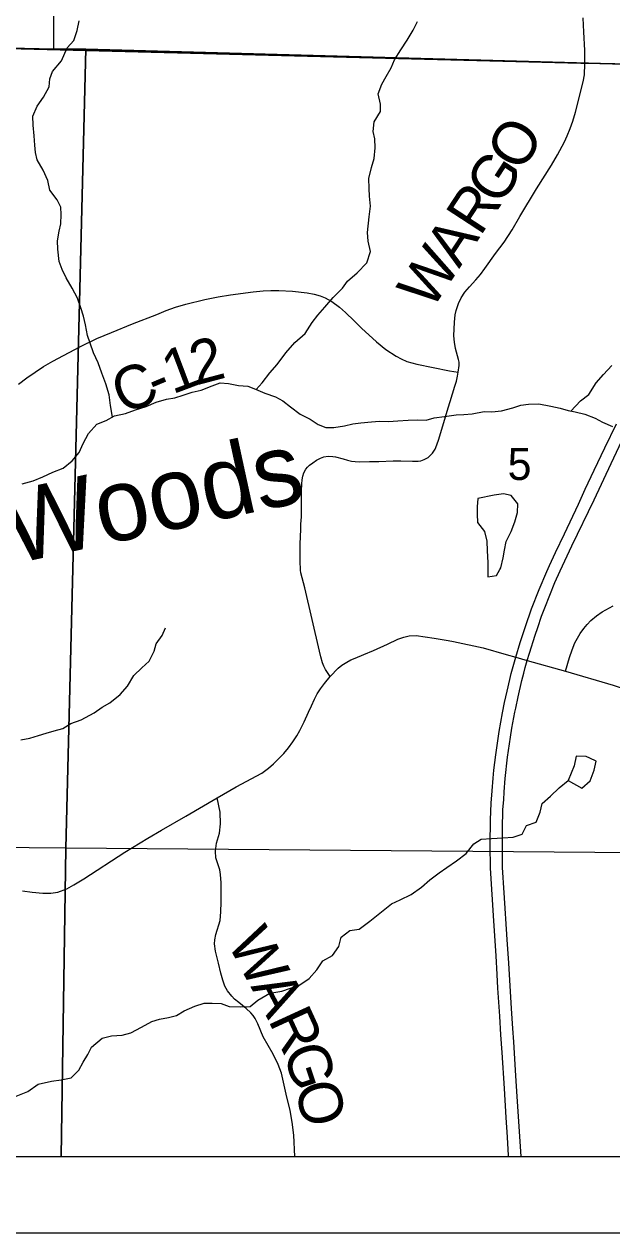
# Model space of a CAD drawing. Extents: x 0 to 34, y 0 to 22.
# Drawn here: x 6.329 to 7.097, y 14 to 15.58 of the extents above; entities that cross this region are included whole.
import ezdxf

# ---------------------------------------------------------------- set-up
doc = ezdxf.new("R2010")
doc.units = 0
for name, color, linetype in [('GM_X_Corporation', 7, 'Continuous'), ('GM_X_County_Road', 7, 'Continuous'), ('GM_X_County_Road_Text', 7, 'Continuous'), ('GM_X_Interstate_Route', 7, 'Continuous'), ('GM_X_Minor_Lake', 7, 'Continuous'), ('GM_X_Minor_River', 7, 'Continuous'), ('GM_X_Minor_River_Text', 7, 'Continuous'), ('GM_X_Section_Text', 7, 'Continuous'), ('SH_Data', 7, 'Continuous')]:
    doc.layers.add(name, color=color, linetype=linetype)

msp = doc.modelspace()

# ---------------------------------------------------------------- linework, layer by layer
at = {"layer": 'GM_X_Corporation'}
for points in [[(5.3699, 17.5116), (5.3543, 16.3597), (5.3453, 15.7118), (5.3483, 15.5723), (5.5099, 15.5686), (5.5173, 15.5684), (5.5624, 15.5674), (5.5643, 15.5673), (5.624, 15.566), (5.6266, 15.5659), (7.0561, 15.5293), (7.0614, 15.5292), (7.2766, 15.5247), (7.2802, 15.5246), (7.2927, 15.5244), (7.5593, 15.5188), (7.5629, 15.5187), (8.3936, 15.4979)], [(8.3936, 15.4979), (7.5629, 15.5187), (7.5593, 15.5188), (7.2927, 15.5244), (7.2802, 15.5246), (7.2766, 15.5247), (7.0614, 15.5292), (7.0561, 15.5293), (5.6266, 15.5659)], [(2.1, 14.1), (8.9, 14.1)], [(4.3124, 14.1), (8.9, 14.1)]]:
    msp.add_lwpolyline(points, dxfattribs=at)
for points in [[(7.3577, 16.5425), (7.3478, 15.5216), (6.4093, 15.5478), (6.3676, 15.5481), (6.3626, 16.5761)], [(5.3476, 15.5712), (6.3676, 15.5481), (6.4093, 15.5478), (6.383, 14.5028), (5.3249, 14.5126), (5.3254, 14.5744)], [(6.4093, 15.5478), (7.3478, 15.5216), (7.4137, 15.5211), (7.3933, 14.4947), (6.383, 14.5028)], [(5.3175, 14.1), (6.3769, 14.1), (6.383, 14.5028), (5.3249, 14.5126)], [(6.3769, 14.1), (7.3859, 14.1), (7.3933, 14.4947), (6.383, 14.5028)]]:
    msp.add_lwpolyline(points, close=True, dxfattribs=at)
at = {"layer": 'GM_X_County_Road'}
for points in [[(7.0616, 15.5316), (7.0616, 15.5461), (7.0601, 15.5705), (7.0597, 15.5792), (7.0593, 15.5885)], [(6.8853, 15.0872), (6.8915, 15.107), (6.8935, 15.1138), (6.895, 15.12), (6.8957, 15.1254), (6.8972, 15.1339), (6.897, 15.1386), (6.8964, 15.1421), (6.8925, 15.1562), (6.8912, 15.1645), (6.89, 15.1727), (6.8909, 15.1908), (6.8919, 15.2002), (6.8933, 15.2061), (6.8963, 15.2151), (6.8996, 15.2227), (6.9047, 15.2298), (6.9107, 15.2369), (6.9191, 15.2459), (6.9251, 15.2531), (6.9306, 15.2611), (6.9448, 15.2807), (6.9561, 15.2952), (6.9663, 15.3116), (6.9765, 15.3287), (6.9984, 15.365), (7.0177, 15.3961), (7.0258, 15.4096), (7.035, 15.4267), (7.0384, 15.4344), (7.0423, 15.4438), (7.0458, 15.4536), (7.0492, 15.4654), (7.0593, 15.505), (7.0608, 15.5142), (7.0616, 15.5287), (7.0616, 15.5316)], [(6.3211, 15.1096), (6.3322, 15.1181), (6.3429, 15.1255), (6.354, 15.1326), (6.3661, 15.1399), (6.4014, 15.1587), (6.4236, 15.1694), (6.4426, 15.1773), (6.4704, 15.1885), (6.502, 15.2006), (6.5142, 15.2061), (6.5262, 15.2105), (6.5401, 15.2141), (6.5649, 15.2205), (6.5822, 15.2238), (6.5985, 15.2266), (6.6281, 15.2306), (6.6408, 15.2316), (6.6509, 15.2321), (6.6616, 15.2321), (6.6793, 15.2315), (6.6983, 15.2291), (6.7076, 15.2272), (6.7154, 15.2251), (6.7222, 15.2224), (6.7306, 15.2179), (6.7408, 15.2102), (6.7488, 15.2034), (6.7598, 15.1924), (6.7696, 15.1831), (6.7891, 15.1649), (6.8013, 15.1549), (6.8149, 15.1461), (6.8214, 15.1426), (6.8288, 15.1394), (6.842, 15.136), (6.8844, 15.1271), (6.8957, 15.1254)], [(6.7286, 14.7275), (6.7223, 14.7366), (6.7202, 14.7408), (6.7186, 14.7452), (6.7162, 14.753), (6.7145, 14.7604), (6.6956, 14.8434), (6.6904, 14.8628), (6.6899, 14.8664), (6.6896, 14.8707), (6.6894, 14.8742), (6.6892, 14.8794), (6.6895, 14.9003), (6.6901, 14.9203), (6.6904, 14.9267), (6.6909, 14.9363), (6.6911, 14.9427), (6.6913, 14.9569), (6.6913, 14.9697), (6.6915, 14.9794), (6.6919, 14.9844), (6.6928, 14.9892), (6.6943, 14.9936), (6.6968, 14.9984), (6.6989, 15.001), (6.7017, 15.0036), (6.7059, 15.007), (6.7108, 15.0103), (6.716, 15.0131), (6.7202, 15.0146), (6.7261, 15.0155), (6.7319, 15.0151), (6.7356, 15.0145), (6.7455, 15.0122), (6.751, 15.0105), (6.7566, 15.0089), (6.7614, 15.0085), (6.7666, 15.0083), (6.7798, 15.0084), (6.792, 15.0085), (6.811, 15.0096), (6.821, 15.0096), (6.8362, 15.0089), (6.8436, 15.009), (6.847, 15.0095), (6.8514, 15.011), (6.8566, 15.014), (6.8594, 15.0163), (6.8625, 15.0196), (6.8656, 15.0248), (6.868, 15.0303), (6.8707, 15.0376), (6.8791, 15.0668), (6.8826, 15.0787), (6.8853, 15.0872)], [(7.0363, 14.7345), (7.0413, 14.7524), (7.0447, 14.7622), (7.0484, 14.7716), (7.0517, 14.7777), (7.0551, 14.7835), (7.0599, 14.79), (7.0645, 14.7955), (7.0694, 14.8005), (7.0767, 14.8068), (7.084, 14.8119), (7.0982, 14.8198)], [(6.7286, 14.7275), (6.739, 14.7382), (6.7438, 14.7421), (6.7502, 14.746), (6.7557, 14.7491), (6.7612, 14.7515), (6.7727, 14.7562), (6.7854, 14.7615), (6.8036, 14.7699), (6.8171, 14.7761), (6.8247, 14.779), (6.8316, 14.7806), (6.841, 14.7809), (6.8644, 14.7777), (6.8828, 14.7743)], [(6.8828, 14.7743), (6.8896, 14.7731), (6.9286, 14.7649), (6.9585, 14.7561), (6.9711, 14.7526), (6.986, 14.7484), (7.0363, 14.7345), (7.0982, 14.716), (7.1152, 14.7105), (7.1287, 14.7049), (7.1395, 14.6983), (7.1586, 14.6855), (7.1616, 14.6831)], [(6.581, 14.5686), (6.6059, 14.583), (6.6394, 14.6012), (6.6481, 14.6075), (6.6546, 14.6132), (6.6679, 14.6268), (6.6742, 14.6342), (6.6796, 14.6418), (6.6849, 14.6499), (6.689, 14.657), (6.6947, 14.6681), (6.7004, 14.6806), (6.7042, 14.689), (6.708, 14.6979), (6.7115, 14.7047), (6.7158, 14.7111), (6.7212, 14.7184), (6.7286, 14.7275)], [(6.3263, 14.4472), (6.3393, 14.4454), (6.353, 14.4441), (6.3636, 14.4443), (6.3728, 14.4455), (6.3842, 14.4498), (6.3937, 14.455), (6.4064, 14.4628), (6.4604, 14.4977), (6.4902, 14.5161), (6.5083, 14.5267), (6.5398, 14.5449), (6.581, 14.5686)], [(6.6825, 14.1), (6.6812, 14.1278), (6.6789, 14.1446), (6.6762, 14.1599), (6.6712, 14.1813), (6.665, 14.2086), (6.6605, 14.2203), (6.6541, 14.2338), (6.641, 14.2563), (6.6342, 14.2731), (6.6306, 14.2804), (6.6279, 14.284), (6.625, 14.2877), (6.6188, 14.2932), (6.6092, 14.3011), (6.6037, 14.3056), (6.5999, 14.3095), (6.5945, 14.3165), (6.5911, 14.3225), (6.5882, 14.3303), (6.5855, 14.3395), (6.5826, 14.3527), (6.5787, 14.3681), (6.5775, 14.378), (6.5777, 14.383), (6.5791, 14.39), (6.5846, 14.4083), (6.5858, 14.4199), (6.5859, 14.4324), (6.5859, 14.4577), (6.5853, 14.4685), (6.5843, 14.4745), (6.5828, 14.4799), (6.5793, 14.4903), (6.5785, 14.4991), (6.5799, 14.5095), (6.584, 14.5227), (6.5851, 14.535), (6.5848, 14.5502), (6.581, 14.5686)]]:
    msp.add_lwpolyline(points, dxfattribs=at)
at = {"layer": 'GM_X_Interstate_Route'}
for points in [[(6.978, 14.1), (6.9728, 14.1782), (6.971, 14.2053), (6.9684, 14.2497), (6.9673, 14.2673), (6.9657, 14.2932), (6.9644, 14.3155), (6.9621, 14.3527), (6.9599, 14.3836), (6.9561, 14.4445), (6.9539, 14.4779), (6.9536, 14.5065), (6.9536, 14.5129), (6.9537, 14.5277), (6.9543, 14.5534), (6.9554, 14.5661), (6.956, 14.5768), (6.9574, 14.5941), (6.9603, 14.622), (6.9641, 14.6481), (6.9661, 14.6597), (6.9699, 14.6806), (6.971, 14.6861), (6.9742, 14.7009), (6.9792, 14.7221), (6.9818, 14.7319), (6.9836, 14.7393), (6.986, 14.7484), (6.9892, 14.758), (6.9966, 14.7815), (6.9998, 14.7915), (7.0049, 14.8062), (7.0091, 14.8173), (7.0222, 14.8502), (7.0292, 14.8655), (7.0446, 14.8984), (7.0734, 14.9583), (7.096, 15.0059), (7.1278, 15.0734)], [(6.9618, 14.1), (6.9617, 14.1009), (6.9605, 14.1251), (6.9586, 14.1507), (6.9562, 14.1887), (6.9532, 14.2357), (6.9518, 14.259), (6.9504, 14.2834), (6.9479, 14.3197), (6.947, 14.3379), (6.9454, 14.3621), (6.9441, 14.3816), (6.9426, 14.4079), (6.9402, 14.4423), (6.9383, 14.477), (6.9377, 14.5074), (6.938, 14.5398), (6.9391, 14.5617), (6.9402, 14.5778), (6.9417, 14.5947), (6.9426, 14.6051), (6.9449, 14.625), (6.9494, 14.6554), (6.9538, 14.6799), (6.9565, 14.6935), (6.9599, 14.7083), (6.9634, 14.7237), (6.9653, 14.7313), (6.9711, 14.7526), (6.977, 14.7717), (6.9838, 14.7927), (6.9918, 14.8161), (7.0017, 14.8413), (7.0117, 14.8649), (7.0153, 14.8724), (7.0229, 14.8897), (7.0346, 14.9141), (7.053, 14.9528), (7.0619, 14.9722), (7.0738, 14.9971), (7.0874, 15.0263), (7.1026, 15.0579)]]:
    msp.add_lwpolyline(points, dxfattribs=at)
at = {"layer": 'GM_X_Minor_Lake'}
for points in [[(6.9216, 14.96), (6.9205, 14.9493), (6.9206, 14.9399), (6.9213, 14.9289), (6.9301, 14.9171), (6.9332, 14.9046), (6.9339, 14.8918), (6.9344, 14.8766), (6.9344, 14.8576), (6.9458, 14.8596), (6.9505, 14.8674)], [(6.9505, 14.8674), (6.9518, 14.8694), (6.9548, 14.8827), (6.9563, 14.8926), (6.9585, 14.904), (6.9653, 14.9169), (6.9698, 14.9298), (6.9736, 14.9419), (6.9739, 14.9533), (6.9652, 14.9639), (6.9549, 14.9661), (6.9428, 14.9646), (6.9216, 14.96)], [(7.0678, 14.6207), (7.0631, 14.623), (7.0502, 14.6233), (7.0473, 14.6108), (7.0397, 14.5914)], [(7.0397, 14.5914), (7.0576, 14.5813), (7.0685, 14.5908), (7.0738, 14.6048), (7.0764, 14.6166), (7.0678, 14.6207)]]:
    msp.add_lwpolyline(points, dxfattribs=at)
at = {"layer": 'GM_X_Minor_River'}
for points in [[(6.4439, 15.0666), (6.4415, 15.0819), (6.4396, 15.0959), (6.4354, 15.1099), (6.4301, 15.1239), (6.4255, 15.1375), (6.4194, 15.1508), (6.4148, 15.1633), (6.4114, 15.1735), (6.4087, 15.1872), (6.406, 15.1985), (6.4029, 15.2095), (6.3983, 15.222), (6.3915, 15.2352), (6.3835, 15.2489), (6.3782, 15.2595), (6.3743, 15.2701), (6.3728, 15.286), (6.3724, 15.297), (6.3742, 15.3099), (6.3765, 15.3194), (6.3772, 15.3315), (6.3764, 15.341), (6.3718, 15.3508), (6.3623, 15.3633), (6.3596, 15.3762), (6.3535, 15.3894), (6.3455, 15.403), (6.3436, 15.4125), (6.3425, 15.422), (6.3417, 15.4345), (6.3405, 15.4485), (6.3401, 15.4599), (6.3457, 15.4732), (6.354, 15.485), (6.3612, 15.4983), (6.3623, 15.5089), (6.3656, 15.5184), (6.3773, 15.5324), (6.3849, 15.5495), (6.3935, 15.559), (6.3977, 15.5723), (6.4007, 15.5848)], [(6.6317, 15.1027), (6.6395, 15.1114), (6.6497, 15.1243), (6.6591, 15.1353), (6.6704, 15.1505), (6.6825, 15.1642), (6.6961, 15.176), (6.7051, 15.1901), (6.7123, 15.2), (6.7217, 15.2103), (6.7323, 15.2228), (6.7447, 15.235), (6.7511, 15.2445), (6.764, 15.2551), (6.7764, 15.2685), (6.7813, 15.2833), (6.7783, 15.2965), (6.7775, 15.3079), (6.7797, 15.3284), (6.7811, 15.3424), (6.78, 15.3553), (6.7796, 15.3655), (6.7791, 15.3788), (6.7825, 15.3928), (6.7859, 15.4046), (6.7873, 15.4186), (6.7869, 15.4304), (6.7846, 15.4399), (6.7861, 15.4528), (6.7944, 15.4664), (6.7944, 15.4759), (6.7913, 15.4895), (6.7962, 15.5021), (6.8018, 15.5119), (6.8082, 15.5233), (6.8128, 15.5336), (6.821, 15.5469), (6.8293, 15.5594), (6.8372, 15.5727), (6.8425, 15.5837)], [(7.0431, 15.0745), (7.0557, 15.0878), (7.0666, 15.0962), (7.0764, 15.1114), (7.0858, 15.1224), (7.0968, 15.1342)], [(6.326, 14.9795), (6.3404, 14.9833), (6.3532, 14.9883), (6.3661, 14.9944), (6.3797, 14.9998), (6.3914, 15.0093), (6.4005, 15.0203), (6.4057, 15.0321), (6.4129, 15.045), (6.4238, 15.0572), (6.4359, 15.0621), (6.4469, 15.0682), (6.4609, 15.0713), (6.4741, 15.0763), (6.4881, 15.0805), (6.501, 15.0862), (6.5146, 15.0901), (6.5256, 15.092), (6.5365, 15.0955), (6.5483, 15.0993), (6.56, 15.102), (6.5744, 15.1074), (6.5849, 15.1116), (6.5956, 15.1105), (6.6088, 15.1079), (6.6209, 15.1071), (6.6308, 15.103), (6.6433, 15.0981), (6.6569, 15.0932), (6.6668, 15.088), (6.6767, 15.08), (6.6892, 15.0706), (6.7025, 15.0638), (6.7127, 15.057), (6.7229, 15.0529), (6.7335, 15.0529), (6.7472, 15.0553), (6.7581, 15.0576), (6.7687, 15.0591), (6.7824, 15.0603), (6.793, 15.0611)], [(6.793, 15.0611), (6.8047, 15.0608), (6.8168, 15.0616), (6.8304, 15.0628), (6.8422, 15.0632), (6.8539, 15.0625), (6.8645, 15.0655), (6.8778, 15.0675), (6.8933, 15.0694), (6.9031, 15.0699), (6.9141, 15.0707), (6.93, 15.0741), (6.9398, 15.0734), (6.9523, 15.0746), (6.9671, 15.0788), (6.9777, 15.0823), (6.9879, 15.0834), (7.0011, 15.0839), (7.0171, 15.0809), (7.0292, 15.0783), (7.0394, 15.0753), (7.0489, 15.0734), (7.0614, 15.0704), (7.0747, 15.0652), (7.0845, 15.0599), (7.0974, 15.0542)], [(6.3244, 14.6446), (6.3361, 14.6466), (6.3474, 14.6504), (6.3573, 14.6535), (6.3679, 14.6562), (6.3792, 14.6596), (6.3898, 14.6661), (6.403, 14.6707), (6.42, 14.6799), (6.4306, 14.6875), (6.4408, 14.6928), (6.454, 14.7039), (6.4635, 14.7149), (6.4718, 14.7286), (6.4823, 14.7389), (6.4921, 14.7476), (6.4985, 14.7605), (6.5012, 14.77), (6.5091, 14.781), (6.5132, 14.7909)], [(6.5863, 14.2997), (6.5965, 14.296), (6.6109, 14.2953), (6.6238, 14.2961), (6.634, 14.3041), (6.6498, 14.3132), (6.6654, 14.3159), (6.6767, 14.3198), (6.6877, 14.3236), (6.7009, 14.3324), (6.7111, 14.3441), (6.719, 14.3555), (6.7315, 14.3628), (6.7398, 14.3742), (6.7431, 14.3864), (6.7541, 14.3951), (6.7666, 14.3971), (6.7802, 14.4073), (6.7957, 14.4199), (6.8089, 14.4302), (6.8199, 14.4352), (6.8346, 14.4424), (6.8478, 14.452), (6.8588, 14.4615), (6.8709, 14.4706), (6.8811, 14.4779), (6.8935, 14.4866), (6.9064, 14.4961), (6.9162, 14.5087), (6.926, 14.5148), (6.9393, 14.5156), (6.9544, 14.5164), (6.9676, 14.5172), (6.9794, 14.5214), (6.985, 14.5325), (6.9979, 14.537), (7.0028, 14.55), (7.0058, 14.5613), (7.0163, 14.5709), (7.0277, 14.5819), (7.0397, 14.5914)], [(6.3137, 14.177), (6.3333, 14.1847), (6.3469, 14.1946), (6.3643, 14.1981), (6.3772, 14.2), (6.3901, 14.2027), (6.3999, 14.2126), (6.4059, 14.2232), (6.4119, 14.2331), (6.4168, 14.2426), (6.4304, 14.2544), (6.4429, 14.2575), (6.4565, 14.2583), (6.4679, 14.2614), (6.4819, 14.269), (6.4955, 14.2763), (6.5057, 14.2793), (6.5174, 14.2816), (6.5276, 14.284), (6.5378, 14.2901), (6.5515, 14.2962), (6.5639, 14.3004), (6.5742, 14.3004), (6.5863, 14.2997)]]:
    msp.add_lwpolyline(points, dxfattribs=at)
at = {"layer": 'SH_Data'}
for p, q in [((2.1, 14.1), (8.9, 14.1)), ((2, 14), (9, 14))]:
    msp.add_line(p, q, dxfattribs=at)

# ---------------------------------------------------------------- texts
at = {"layer": 'GM_X_County_Road_Text'}
for s, rotation, p in [('O', 59.3741, (6.9789, 15.3853)), ('G', 56.9469, (6.9502, 15.3411)), ('R', 56.8652, (6.9247, 15.302)), ('A', 56.7204, (6.8971, 15.26)), ('W', 56.5977, (6.8608, 15.205)), ('1', 20.662, (6.5223, 15.0961)), ('2', 14.8516, (6.5536, 15.108)), ('C', 23.1053, (6.4584, 15.069)), ('-', 22.764, (6.5012, 15.0873)), ('W', 298.0264, (6.5931, 14.3801)), ('A', 297.9011, (6.6241, 14.3221)), ('R', 294.6762, (6.6471, 14.2786)), ('G', 288.5167, (6.666, 14.2377)), ('O', 284.2925, (6.6815, 14.1914))]:
    msp.add_text(s, height=0.0568, rotation=rotation, dxfattribs=at).set_placement(p)
at = {"layer": 'GM_X_Minor_River_Text'}
msp.add_text('Woods', height=0.09469, rotation=12.212, dxfattribs=at).set_placement((6.3139, 14.874))
at = {"layer": 'GM_X_Section_Text'}
msp.add_text('5', height=0.0419, rotation=0, dxfattribs=at).set_placement((6.9605, 14.9844))

doc.saveas('drawing.dxf')
